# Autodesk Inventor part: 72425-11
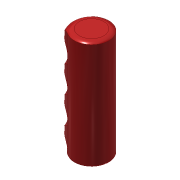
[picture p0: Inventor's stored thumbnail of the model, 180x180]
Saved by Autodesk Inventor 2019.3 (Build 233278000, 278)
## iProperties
Created: 2012-10
Part Number: 72425-11
Material: Ogólny
Document SubType Name: Modeling
Designer: CADENGINEERING4
Density: 1 g/cm^3
Appearance: Jasnoczerwona
Author: CADENGINEERING4
Revision Number: ÈÎºÎ
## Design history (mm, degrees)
feature "ÊäÈë1"
node "Bryła1"
